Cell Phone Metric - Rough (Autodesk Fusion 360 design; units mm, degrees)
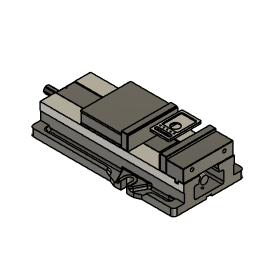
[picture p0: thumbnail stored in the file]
description: HaasClamp
derived_base_feature "Derived Base Feature" bodies "Main Body"
align "Align1"
sketch "Sketch1" plane through (0, 0, 0) normal (0, 0, -1) x axis (1, 0, 0)
  line L1 (30, 46.5) -> (30, -46.5)
  line L2 (-26.5, 50) -> (26.5, 50)
  line L3 (-30, -46.5) -> (-30, 46.5)
  line L4 (26.5, -50) -> (-26.5, -50)
  line L5 (-23.5, 38.5) -> (-23.5, 36)
  line L6 (20, 42) -> (-20, 42)
  line L7 (23.5, 36) -> (23.5, 38.5)
  line L8 (-20, 32.5) -> (20, 32.5)
  line L9 (-50.8, -55) -> (50.8, -55)
  line L10 (-50.8, 55) -> (-50.8, -55)
  line L11 (50.8, 55) -> (-50.8, 55)
  line L12 (50.8, -55) -> (50.8, 55)
  line L13 (-50.8, 55) -> (50.8, -55)
  line L14 (50.8, 55) -> (-50.8, -55)
  arc A1 centre (26.5, -46.5) radius 3.5 clockwise from (30, -46.5) to (26.5, -50)
  arc A2 centre (26.5, 46.5) radius 3.5 clockwise from (26.5, 50) to (30, 46.5)
  arc A3 centre (-26.5, 46.5) radius 3.5 clockwise from (-30, 46.5) to (-26.5, 50)
  arc A4 centre (-26.5, -46.5) radius 3.5 clockwise from (-26.5, -50) to (-30, -46.5)
  circle C1 centre (10.5, 25) radius 2.117
  circle C2 centre (-10.5, 25) radius 2.117
  circle C3 centre (-21, 25) radius 2.117
  circle C4 centre (0, 25) radius 2.117
  circle C5 centre (21, 25) radius 2.117
  arc A5 centre (-20, 38.5) radius 3.5 clockwise from (-23.5, 38.5) to (-20, 42)
  arc A6 centre (20, 38.5) radius 3.5 clockwise from (20, 42) to (23.5, 38.5)
  arc A7 centre (20, 36) radius 3.5 clockwise from (23.5, 36) to (20, 32.5)
  arc A8 centre (-20, 36) radius 3.5 clockwise from (-20, 32.5) to (-23.5, 36)
  circle C6 centre (0, 0) radius 12.5
  point P36 (0, 0)
  point P1 (0, 0)
  point P34 (-50.8, 55)
  point P35 (50.8, 55)
  point P32 (50.8, -55)
  horizontal L9
  perpendicular L9 L10
  parallel L9 L11
  parallel L10 L12
  coincident L13 P36
  coincident L14 P36
  coincident P1 P36
  dimension "d1" distance P34 P35 = 101.6
  dimension "d2" distance P32 P35 = 110
extrude "Extrude1" new body sketch "Sketch1" profile of L9 L10 L11 L12 against normal blind 6 bodies "Stock"
base_feature "Base Feature1"
base_feature "Base Feature1"
base_feature "Base Feature1"
base_feature "Base Feature1"
base_feature "Base Feature1"
base_feature "Base Feature1"
base_feature "Base Feature1"
base_feature "Base Feature1"
base_feature "Base Feature1"
base_feature "Base Feature1"
as_built_joint "As-built1"
as_built_joint "As-built2"
as_built_joint "As-built3"
joint_origin "JointOrigin1" OffsetX 0 OffsetY 0 OffsetZ 0 AngleZ 0
joint "Assemble1" alignAngle 180 alignOffsetX 0 alignOffsetY 0 alignOffsetZ 0 (= "jaw_width_haas_050002") SlideMaximum 22.5 SlideMinimum 0
position "Position1"
sketch "Sketch1" plane through (0, -72.5, 0) normal (0, -1, 0) x axis (1, 0, 0)
  line L1 (75, 73) -> (-75, 73)
  line L2 (76, 74) -> (75, 73)
  line L3 (76, 116.5) -> (76, 74)
  line L4 (75, 117.5) -> (76, 116.5)
  line L5 (-75, 117.5) -> (75, 117.5)
  line L6 (-76, 116.5) -> (-75, 117.5)
  line L7 (-76, 74) -> (-76, 116.5)
  line L8 (-75, 73) -> (-76, 74)
  line L9 (76.4, 114.275) -> (-76, 114.275)
  line L10 (76.4, 73) -> (76.4, 114.275)
  line L11 (-76, 73) -> (76.4, 73)
  line L12 (-76, 114.275) -> (-76, 73)
  circle C1 centre (49.21, 96.8) radius 11
  circle C2 centre (-49.21, 96.8) radius 11
  point P14 (76.4, 73)
  point P12 (-76, 114.275)
  point P13 (76.4, 114.275)
  horizontal L9
  vertical L10
  horizontal L11
  vertical L12
  coincident L1 P14
  coincident L7 P12
  dimension "d16" distance P12 P13 = 152.4
  dimension "d17" distance P13 P14 = 41.275
place_component sketch "Sketch1"
extrude "Extrude1" new body sketch "Sketch1" profile of L1 L2 L3 L7 L8 C1 C2 L9 L11 L12 along normal blind 3.175
place_component sketch "Sketch1"
extrude "Extrude1" sketch "Sketch1" profile of L1 L2 L3 L7 L8 C1 C2 L9 L11 L12 blind -3.175
as_built_joint "As-built5"
as_built_joint "As-built6"
position "Position1"
ground "Pin"
position "Position2"
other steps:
create_component "CreateComponent1"
create_component "CreateComponent2"
create_component "CreateComponent3"
create_component "CreateComponent4"
create_component "CreateComponent5"
create_component "CreateComponent6"
create_component "CreateComponent7"
create_component "CreateComponent8"
create_component "CreateComponent9"
create_component "CreateComponent10"
joint_origin "JointOrigin10"
joint_origin "JointOrigin11"
create_component "CreateComponent11" sketch "Sketch1"
create_component "CreateComponent12" sketch "Sketch1"
create_component "CreateComponent1"
named bodies: "Main Body", "Stock"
